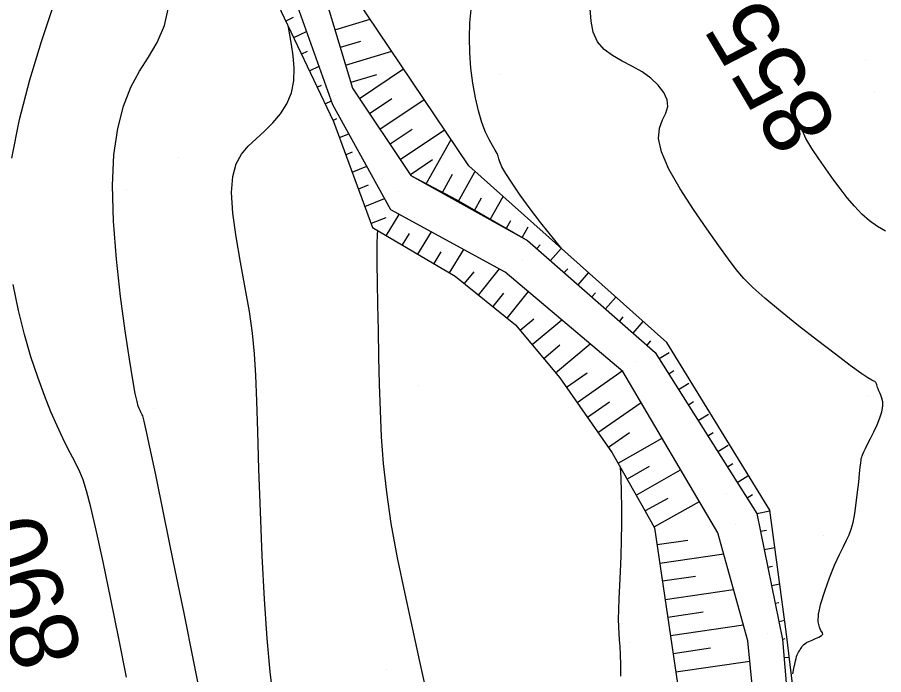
# Model space of a CAD drawing. Extents: x 400243 to 403697, y 4403637 to 4408083.
# Drawn here: x 402859.8 to 402954.4, y 4405923.8 to 4405995.5 of the extents above; entities that cross this region are included whole.
import ezdxf

# ---------------------------------------------------------------- set-up
doc = ezdxf.new("R2010")
doc.units = 0
doc.layers.add('HH_IC', color=7, linetype='Continuous')

msp = doc.modelspace()

# ---------------------------------------------------------------- linework, layer by layer
at = {"layer": 'HH_IC'}
for p, q in [((402872.494, 4406030.158), (402894.337, 4405984.152)), ((402890.906, 4406006.012), (402896.405, 4405987.776)), ((402890.906, 4406006.012), (402896.405, 4405987.776)), ((402894.245, 4405985.987), (402887.242, 4406005.626)), ((402894.245, 4405985.987), (402887.242, 4406005.626)), ((402894.245, 4405985.987), (402887.242, 4406005.626)), ((402909.104, 4405979.306), (402894.443, 4406001.103)), ((402889.93, 4405995.485), (402889.135, 4405995.108)), ((402894.486, 4405994.139), (402898.344, 4405995.303)), ((402889.993, 4405993.301), (402891.399, 4405993.969)), ((402897.288, 4405992.895), (402895.064, 4405992.224)), ((402891.463, 4405991.785), (402890.851, 4405991.494)), ((402895.641, 4405990.31), (402900.681, 4405991.829)), ((402952.365, 4405990.924), (402952.365, 4405990.924)), ((402891.709, 4405989.688), (402892.749, 4405990.182)), ((402897.158, 4405986.651), (402901.987, 4405989.887)), ((402899.034, 4405989.244), (402896.218, 4405988.395)), ((402912.565, 4405989.326), (402912.565, 4405989.326)), ((402892.995, 4405988.085), (402892.567, 4405987.881)), ((402894.567, 4405987.023), (402894.567, 4405987.023)), ((402896.405, 4405987.776), (402902.77, 4405978.276)), ((402896.405, 4405987.776), (402902.77, 4405978.276)), ((402896.405, 4405987.776), (402896.405, 4405987.776)), ((402953.392, 4405987.431), (402953.392, 4405987.431)), ((402893.424, 4405986.074), (402894.1, 4405986.395)), ((402894.245, 4405985.987), (402894.245, 4405985.987)), ((402900.59, 4405974.511), (402894.245, 4405985.987)), ((402900.59, 4405974.511), (402894.245, 4405985.987)), ((402900.59, 4405974.511), (402894.245, 4405985.987)), ((402900.688, 4405986.608), (402898.272, 4405984.99)), ((402899.385, 4405983.328), (402904.22, 4405986.568)), ((402894.644, 4405984.439), (402894.282, 4405984.268)), ((402894.337, 4405984.152), (402894.337, 4405984.152)), ((402894.337, 4405984.152), (402898.593, 4405972.572)), ((402894.337, 4405984.152), (402898.593, 4405972.572)), ((402902.917, 4405983.287), (402900.498, 4405981.667)), ((402901.611, 4405980.005), (402906.452, 4405983.249)), ((402894.983, 4405982.394), (402896.003, 4405982.807)), ((402904.446, 4405977.342), (402907.156, 4405982.202)), ((402896.384, 4405980.803), (402895.673, 4405980.516)), ((402877.447, 4405980.181), (402877.447, 4405980.181)), ((402905.147, 4405979.966), (402902.725, 4405978.344)), ((402896.364, 4405978.638), (402897.953, 4405979.281)), ((402907.939, 4405975.393), (402909.751, 4405978.643)), ((402909.104, 4405979.306), (402909.104, 4405979.306)), ((402930.702, 4405960.023), (402909.104, 4405979.306)), ((402909.104, 4405979.306), (402909.104, 4405979.306)), ((402902.77, 4405978.276), (402915.521, 4405971.165)), ((402902.77, 4405978.276), (402907.722, 4405975.628)), ((402902.77, 4405978.276), (402902.77, 4405978.276)), ((402907.3, 4405978.354), (402906.192, 4405976.367)), ((402871.787, 4405976.687), (402871.787, 4405976.687)), ((402898.109, 4405977.186), (402897.054, 4405976.759)), ((402901.404, 4405976.55), (402901.404, 4405976.55)), ((402897.744, 4405974.881), (402899.902, 4405975.755)), ((402907.722, 4405975.628), (402907.722, 4405975.628)), ((402907.722, 4405975.628), (402915.521, 4405971.165)), ((402910.447, 4405975.784), (402909.686, 4405974.419)), ((402911.433, 4405973.445), (402912.841, 4405975.97)), ((402900.09, 4405971.692), (402901.51, 4405974.011)), ((402900.59, 4405974.511), (402900.59, 4405974.511)), ((402913.065, 4405967.727), (402900.59, 4405974.511)), ((402913.065, 4405967.727), (402900.59, 4405974.511)), ((402913.065, 4405967.727), (402900.59, 4405974.511)), ((402900.026, 4405973.647), (402898.435, 4405973.003)), ((402913.651, 4405973.316), (402913.179, 4405972.471)), ((402898.593, 4405972.572), (402898.593, 4405972.572)), ((402898.593, 4405972.572), (402907.611, 4405967.275)), ((402898.593, 4405972.572), (402907.611, 4405967.275)), ((402902.575, 4405971.919), (402901.815, 4405970.679)), ((402903.54, 4405969.666), (402905.029, 4405972.097)), ((402914.926, 4405971.497), (402915.579, 4405972.667)), ((402915.521, 4405971.165), (402929.441, 4405958.945)), ((402915.521, 4405971.165), (402929.441, 4405958.945)), ((402915.521, 4405971.165), (402915.521, 4405971.165)), ((402906.04, 4405969.918), (402905.265, 4405968.653)), ((402906.997, 4405967.651), (402908.547, 4405970.184)), ((402916.871, 4405970.704), (402916.512, 4405970.295)), ((402918.015, 4405968.976), (402919.184, 4405970.307)), ((402914.948, 4405969.062), (402914.948, 4405969.062)), ((402910.162, 4405965.215), (402912.458, 4405968.057)), ((402919.89, 4405968.08), (402919.518, 4405967.656)), ((402907.611, 4405967.275), (402907.611, 4405967.275)), ((402907.611, 4405967.275), (402914.211, 4405961.945)), ((402907.611, 4405967.275), (402914.211, 4405961.945)), ((402909.639, 4405967.75), (402908.606, 4405966.471)), ((402913.065, 4405967.727), (402913.065, 4405967.727)), ((402925.915, 4405956.862), (402913.065, 4405967.727)), ((402925.915, 4405956.862), (402913.065, 4405967.727)), ((402925.915, 4405956.862), (402913.065, 4405967.727)), ((402921.021, 4405966.337), (402922.168, 4405967.643)), ((402912.896, 4405965.416), (402911.718, 4405963.958)), ((402913.274, 4405962.701), (402915.601, 4405965.583)), ((402922.909, 4405965.455), (402922.524, 4405965.017)), ((402924.027, 4405963.698), (402925.151, 4405964.979)), ((402916.205, 4405962.576), (402914.722, 4405961.335)), ((402916.006, 4405959.801), (402919.238, 4405962.507)), ((402925.927, 4405962.831), (402925.53, 4405962.378)), ((402914.211, 4405961.945), (402914.211, 4405961.945)), ((402914.211, 4405961.945), (402919.038, 4405956.18)), ((402914.211, 4405961.945), (402919.038, 4405956.18)), ((402927.033, 4405961.059), (402928.135, 4405962.314)), ((402919.039, 4405959.732), (402917.29, 4405958.268)), ((402918.574, 4405956.734), (402922.338, 4405959.886)), ((402928.946, 4405960.206), (402928.536, 4405959.739)), ((402930.702, 4405960.023), (402930.702, 4405960.023)), ((402941.958, 4405941.73), (402930.702, 4405960.023)), ((402929.441, 4405958.945), (402940.532, 4405941.356)), ((402929.441, 4405958.945), (402940.532, 4405941.356)), ((402929.441, 4405958.945), (402929.441, 4405958.945)), ((402929.866, 4405958.272), (402930.958, 4405958.96)), ((402927.338, 4405957.934), (402927.338, 4405957.934)), ((402922.014, 4405956.696), (402919.768, 4405955.132)), ((402920.91, 4405953.491), (402925.842, 4405956.924)), ((402925.915, 4405956.862), (402925.915, 4405956.862)), ((402936.284, 4405939.249), (402925.915, 4405956.862)), ((402936.284, 4405939.249), (402925.915, 4405956.862)), ((402936.284, 4405939.249), (402925.915, 4405956.862)), ((402931.483, 4405956.927), (402930.932, 4405956.58)), ((402919.038, 4405956.18), (402919.038, 4405956.18)), ((402919.038, 4405956.18), (402924.745, 4405947.983)), ((402903.594, 4405955.293), (402903.594, 4405955.293)), ((402931.999, 4405954.888), (402933.11, 4405955.589)), ((402952.603, 4405954.16), (402952.603, 4405954.16)), ((402924.469, 4405953.531), (402922.053, 4405951.849)), ((402923.196, 4405950.208), (402927.903, 4405953.485)), ((402933.626, 4405953.55), (402933.066, 4405953.197)), ((402874.66, 4405952.882), (402874.66, 4405952.882)), ((402934.133, 4405951.505), (402935.263, 4405952.217)), ((402926.63, 4405950.161), (402924.339, 4405948.566)), ((402935.769, 4405950.172), (402935.199, 4405949.813)), ((402925.383, 4405946.863), (402930.19, 4405949.601)), ((402936.266, 4405948.121), (402937.415, 4405948.846)), ((402924.745, 4405947.983), (402924.745, 4405947.983)), ((402924.745, 4405947.983), (402928.316, 4405941.714)), ((402952.239, 4405947.653), (402952.239, 4405947.653)), ((402928.789, 4405946.501), (402926.373, 4405945.125)), ((402937.912, 4405946.795), (402937.333, 4405946.43)), ((402927.363, 4405943.387), (402932.219, 4405946.154)), ((402938.4, 4405944.738), (402939.567, 4405945.474)), ((402937.188, 4405943.536), (402937.188, 4405943.536)), ((402930.804, 4405943.021), (402928.352, 4405941.649)), ((402929.329, 4405939.904), (402934.271, 4405942.669)), ((402940.055, 4405943.417), (402939.466, 4405943.046)), ((402928.316, 4405941.714), (402928.316, 4405941.714)), ((402928.316, 4405941.714), (402929.379, 4405939.814)), ((402940.532, 4405941.354), (402941.969, 4405941.648)), ((402943.786, 4405928.193), (402941.958, 4405941.73)), ((402942.052, 4405941.717), (402942.052, 4405941.717)), ((402940.532, 4405941.356), (402940.532, 4405941.356)), ((402940.532, 4405941.356), (402943.342, 4405927.638)), ((402940.532, 4405941.356), (402943.342, 4405927.638)), ((402929.379, 4405939.814), (402929.379, 4405939.814)), ((402929.379, 4405939.814), (402939.345, 4405871.783)), ((402938.203, 4405940.173), (402938.203, 4405940.173)), ((402936.284, 4405939.249), (402936.284, 4405939.249)), ((402939.568, 4405927.469), (402936.284, 4405939.249)), ((402939.568, 4405927.469), (402936.284, 4405939.249)), ((402939.568, 4405927.469), (402936.284, 4405939.249)), ((402941.585, 4405939.528), (402940.934, 4405939.395)), ((402947.796, 4405938.989), (402947.796, 4405938.989)), ((402933.015, 4405938.429), (402929.654, 4405937.937)), ((402929.944, 4405935.958), (402936.917, 4405936.979)), ((402941.335, 4405937.435), (402942.505, 4405937.675)), ((402942.255, 4405935.582), (402941.736, 4405935.476)), ((402933.846, 4405934.508), (402930.234, 4405933.979)), ((402930.524, 4405932), (402937.999, 4405933.095)), ((402942.138, 4405933.517), (402943.042, 4405933.702)), ((402942.925, 4405931.636), (402942.539, 4405931.557)), ((402934.677, 4405930.587), (402930.814, 4405930.021)), ((402942.94, 4405929.598), (402943.579, 4405929.729)), ((402931.103, 4405928.042), (402939.082, 4405929.211)), ((402939.568, 4405927.469), (402939.568, 4405927.469)), ((402941.426, 4405908.372), (402939.568, 4405927.469)), ((402941.426, 4405908.372), (402939.568, 4405927.469)), ((402941.426, 4405908.372), (402939.568, 4405927.469)), ((402941.731, 4405928.301), (402941.731, 4405928.301)), ((402943.591, 4405927.69), (402943.342, 4405927.639)), ((402943.342, 4405927.638), (402943.342, 4405927.638)), ((402943.342, 4405927.638), (402944.913, 4405908.491)), ((402943.342, 4405927.638), (402944.913, 4405908.491)), ((402947.491, 4405896.893), (402943.786, 4405928.193)), ((402943.786, 4405928.193), (402943.786, 4405928.193)), ((402926.598, 4405927.323), (402926.598, 4405927.323)), ((402935.491, 4405926.664), (402931.393, 4405926.064)), ((402943.505, 4405925.645), (402944.082, 4405925.693)), ((402931.683, 4405924.085), (402939.782, 4405925.271)), ((402900.103, 4405924.329), (402900.103, 4405924.329))]:
    msp.add_line(p, q, dxfattribs=at)
for points in [[(402859.218, 4405980.137), (402860.065, 4405984.37), (402861.199, 4405988.707), (402862.462, 4405992.876), (402863.697, 4405996.607), (402864.747, 4405999.628), (402865.491, 4406001.749), (402865.948, 4406003.103), (402866.175, 4406003.905), (402866.228, 4406004.369), (402866.162, 4406004.711), (402866.021, 4406005.123), (402865.794, 4406005.703), (402865.458, 4406006.53), (402864.991, 4406007.68), (402864.369, 4406009.231), (402863.581, 4406011.213), (402862.665, 4406013.475), (402861.67, 4406015.817), (402860.645, 4406018.04), (402859.641, 4406019.947)], [(402879.981, 4405920.623), (402879.086, 4405925.178), (402878.015, 4405930.507), (402876.886, 4405936.055), (402875.816, 4405941.266), (402874.923, 4405945.586), (402874.295, 4405948.599), (402873.9, 4405950.458), (402873.677, 4405951.454), (402873.567, 4405951.88), (402873.507, 4405952.028), (402873.447, 4405952.142), (402873.377, 4405952.275), (402873.299, 4405952.43), (402873.214, 4405952.612), (402873.121, 4405952.824), (402873.019, 4405953.1), (402872.886, 4405953.592), (402872.701, 4405954.484), (402872.438, 4405955.959), (402872.075, 4405958.197), (402871.606, 4405961.302), (402871.097, 4405965.052), (402870.636, 4405969.145), (402870.306, 4405973.279), (402870.194, 4405977.152), (402870.363, 4405980.523), (402870.789, 4405983.395), (402871.427, 4405985.83), (402872.23, 4405987.892), (402873.154, 4405989.646), (402874.141, 4405991.188), (402875.09, 4405992.758), (402875.888, 4405994.629), (402876.423, 4405997.074)], [(402919.257, 4405970.242), (402916.945, 4405973.098), (402915.779, 4405974.638), (402914.717, 4405976.102), (402913.817, 4405977.405), (402913.136, 4405978.464), (402912.708, 4405979.222), (402912.479, 4405979.736), (402912.367, 4405980.09), (402912.295, 4405980.37), (402912.183, 4405980.658), (402911.969, 4405981.032), (402911.667, 4405981.528), (402911.303, 4405982.176), (402910.909, 4405983.003), (402910.514, 4405984.04), (402910.143, 4405985.299), (402909.814, 4405986.743), (402909.54, 4405988.319), (402909.334, 4405989.975), (402909.209, 4405991.657), (402909.175, 4405993.315), (402909.224, 4405994.907), (402909.346, 4405996.392)], [(402944.475, 4405923.886), (402944.573, 4405924.453), (402944.665, 4405924.917), (402944.745, 4405925.281), (402944.814, 4405925.561), (402944.877, 4405925.778), (402944.941, 4405925.952), (402945.011, 4405926.104), (402945.09, 4405926.251), (402945.176, 4405926.394), (402945.265, 4405926.534), (402945.356, 4405926.669), (402945.443, 4405926.798), (402945.527, 4405926.921), (402945.625, 4405927.04), (402945.759, 4405927.16), (402945.947, 4405927.285), (402946.211, 4405927.419), (402946.559, 4405927.564), (402946.943, 4405927.719), (402947.305, 4405927.879), (402947.585, 4405928.041), (402947.723, 4405928.2), (402947.684, 4405928.366), (402947.533, 4405928.597), (402947.356, 4405928.962), (402947.243, 4405929.532), (402947.28, 4405930.378), (402947.529, 4405931.534), (402947.949, 4405932.899), (402948.471, 4405934.339), (402949.027, 4405935.717), (402949.548, 4405936.897), (402949.981, 4405937.787), (402950.328, 4405938.463), (402950.608, 4405939.045), (402950.838, 4405939.652), (402951.037, 4405940.404), (402951.219, 4405941.382), (402951.384, 4405942.516), (402951.529, 4405943.694), (402951.652, 4405944.808), (402951.749, 4405945.748), (402951.819, 4405946.434), (402951.869, 4405946.894), (402951.907, 4405947.189), (402951.939, 4405947.378), (402951.976, 4405947.52), (402952.025, 4405947.668), (402952.1, 4405947.855), (402952.216, 4405948.112), (402952.387, 4405948.465), (402952.629, 4405948.943), (402952.946, 4405949.561), (402953.304, 4405950.279), (402953.659, 4405951.042), (402953.968, 4405951.795), (402954.185, 4405952.485), (402954.28, 4405953.069), (402954.273, 4405953.55), (402954.195, 4405953.945), (402954.079, 4405954.271), (402953.955, 4405954.542), (402953.852, 4405954.774), (402953.77, 4405954.972), (402953.706, 4405955.14), (402953.656, 4405955.284), (402953.615, 4405955.408), (402953.581, 4405955.514), (402953.548, 4405955.604), (402953.511, 4405955.677), (402953.463, 4405955.733), (402953.4, 4405955.771), (402953.301, 4405955.807), (402953.084, 4405955.912), (402952.648, 4405956.176), (402951.897, 4405956.685), (402950.732, 4405957.527), (402949.103, 4405958.752), (402947.159, 4405960.249), (402945.096, 4405961.869), (402943.112, 4405963.464), (402941.403, 4405964.885), (402940.108, 4405966.035), (402939.122, 4405967.019), (402938.283, 4405967.998), (402937.429, 4405969.128), (402936.397, 4405970.569), (402935.083, 4405972.421), (402933.613, 4405974.557), (402932.172, 4405976.793), (402930.946, 4405978.945), (402930.119, 4405980.829), (402929.817, 4405982.309), (402929.917, 4405983.439), (402930.237, 4405984.326), (402930.596, 4405985.071), (402930.812, 4405985.78), (402930.739, 4405986.534), (402930.382, 4405987.321), (402929.783, 4405988.11), (402928.983, 4405988.866), (402928.025, 4405989.558), (402926.957, 4405990.167), (402925.853, 4405990.74), (402924.795, 4405991.339), (402923.865, 4405992.025), (402923.144, 4405992.861), (402922.688, 4405993.891), (402922.444, 4405995.094), (402922.335, 4405996.431)], [(402887.787, 4405921.151), (402887.43, 4405924.109), (402887.094, 4405927.737), (402886.804, 4405932.04), (402886.559, 4405936.765), (402886.357, 4405941.599), (402886.194, 4405946.224), (402886.065, 4405950.327), (402885.962, 4405953.682), (402885.854, 4405956.432), (402885.707, 4405958.814), (402885.486, 4405961.06), (402885.155, 4405963.405), (402884.7, 4405966.017), (402884.188, 4405968.793), (402883.709, 4405971.561), (402883.351, 4405974.15), (402883.201, 4405976.39), (402883.328, 4405978.158), (402883.705, 4405979.518), (402884.288, 4405980.582), (402885.028, 4405981.464), (402885.88, 4405982.275), (402886.794, 4405983.112), (402887.704, 4405984.011), (402888.544, 4405984.99), (402889.246, 4405986.068), (402889.741, 4405987.266), (402889.986, 4405988.584), (402890.024, 4405989.96), (402889.922, 4405991.312), (402889.747, 4405992.56), (402889.566, 4405993.622), (402889.429, 4405994.449), (402889.42, 4405994.509)], [(402954.585, 4405972.192), (402953.706, 4405972.689), (402952.847, 4405973.315), (402952.01, 4405974.057), (402951.192, 4405974.901), (402950.395, 4405975.835), (402949.612, 4405976.839), (402948.839, 4405977.896), (402948.07, 4405978.986), (402947.3, 4405980.091), (402946.541, 4405981.196), (402945.874, 4405982.294), (402945.399, 4405983.386)], [(402904.421, 4405922.264), (402903.769, 4405925.238), (402902.979, 4405928.765), (402902.137, 4405932.607), (402901.328, 4405936.524), (402900.639, 4405940.281), (402900.135, 4405943.696), (402899.797, 4405946.817), (402899.583, 4405949.75), (402899.454, 4405952.601), (402899.368, 4405955.475), (402899.293, 4405958.434), (402899.225, 4405961.375), (402899.168, 4405964.151), (402899.126, 4405966.614), (402899.103, 4405968.618), (402899.102, 4405970.06), (402899.115, 4405971.015), (402899.134, 4405971.601), (402899.15, 4405971.937), (402899.155, 4405972.142), (402899.148, 4405972.246)], [(402871.741, 4405923.521), (402870.917, 4405927.715), (402870.039, 4405932.032), (402869.184, 4405936.098), (402868.434, 4405939.539), (402867.844, 4405942.081), (402867.386, 4405943.845), (402867.008, 4405945.053), (402866.66, 4405945.925), (402866.288, 4405946.682), (402865.853, 4405947.512), (402865.35, 4405948.476), (402864.785, 4405949.603), (402864.164, 4405950.921), (402863.493, 4405952.459), (402862.78, 4405954.238), (402862.047, 4405956.251), (402861.314, 4405958.482), (402860.606, 4405960.918), (402859.944, 4405963.543), (402859.361, 4405966.352)], [(402925.685, 4405923.608), (402925.683, 4405924.87), (402925.659, 4405925.974), (402925.613, 4405926.863), (402925.556, 4405927.601), (402925.502, 4405928.28), (402925.462, 4405928.993), (402925.448, 4405929.832), (402925.469, 4405930.871), (402925.518, 4405932.104), (402925.582, 4405933.505), (402925.652, 4405935.051), (402925.714, 4405936.715), (402925.76, 4405938.467), (402925.784, 4405940.254), (402925.786, 4405942.02), (402925.763, 4405943.707), (402925.712, 4405945.256), (402925.645, 4405946.403)]]:
    msp.add_lwpolyline(points, dxfattribs=at)

# ---------------------------------------------------------------- texts
for s, rotation, p in [('855', 120.65456, (402949.559, 4405983.721)), ('890', 107.22816, (402867.079, 4405925.875))]:
    msp.add_text(s, height=7.5, rotation=rotation, dxfattribs=at).set_placement(p)

doc.saveas('drawing.dxf')
